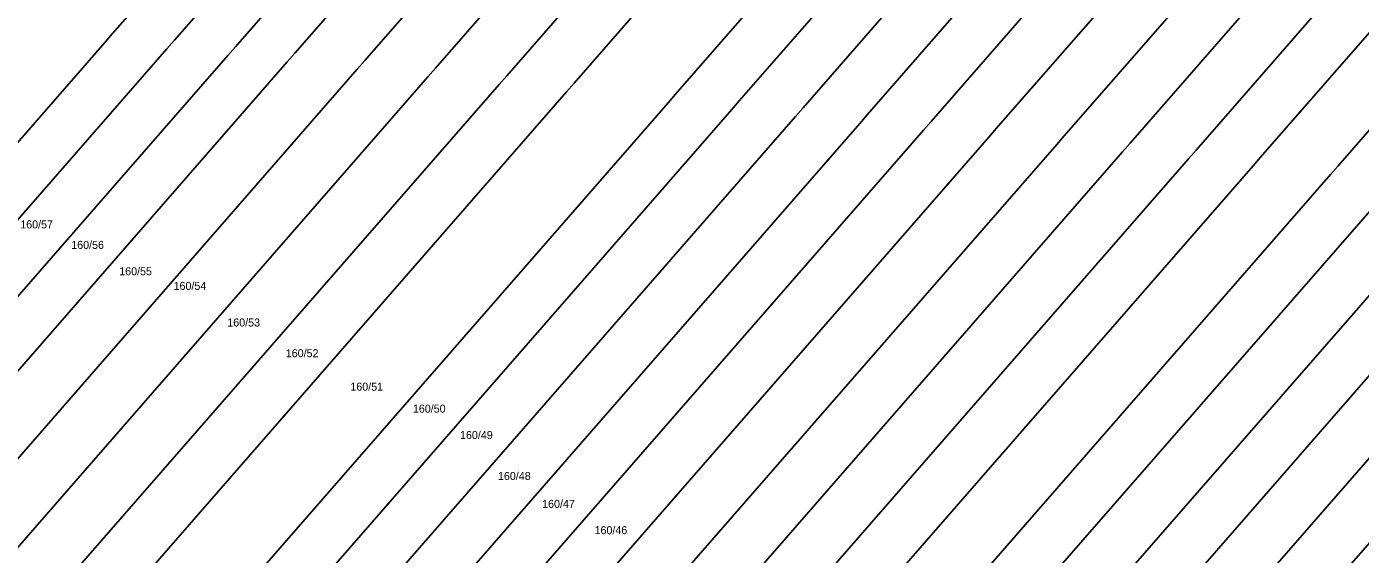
# Model space of a CAD drawing. Extents: x -580630 to -576196, y -1189024 to -1183567.
# Drawn here: x -579205 to -578921.7, y -1186434.7 to -1186322.7 of the extents above; entities that cross this region are included whole.
import ezdxf

# ---------------------------------------------------------------- set-up
doc = ezdxf.new("R2010")
doc.units = 0
doc.layers.add('Vrstva 1', color=7, linetype='Continuous')
doc.layers.add('Vrstva 18', color=7, linetype='Continuous')

msp = doc.modelspace()

# ---------------------------------------------------------------- linework, layer by layer
at = {"layer": 'Vrstva 1'}
for p, q in [((-579072.75, -1186193.55), (-579186.75, -1186324.12)), ((-579173.64, -1186325.54), (-579064.19, -1186200.17)), ((-579055.7, -1186206.72), (-579160.66, -1186326.94)), ((-579148.04, -1186328.3), (-579047.45, -1186213.09)), ((-579037.75, -1186220.59), (-579133.17, -1186329.9)), ((-579118.17, -1186331.51), (-579027.95, -1186228.17)), ((-579018.06, -1186235.81), (-579103.03, -1186333.14)), ((-579088.71, -1186334.68), (-579008.7, -1186243.04)), ((-578994.61, -1186253.92), (-579067.14, -1186336.99)), ((-579053.63, -1186338.44), (-578985.79, -1186260.74)), ((-578976.94, -1186267.58), (-579040.08, -1186339.9)), ((-579026.43, -1186341.37), (-578968.02, -1186274.47)), ((-579012.88, -1186342.83), (-578959.17, -1186281.31)), ((-578950.11, -1186288.31), (-578999.01, -1186344.32)), ((-578940.68, -1186295.6), (-578984.57, -1186345.87)), ((-578970.56, -1186347.38), (-578931.53, -1186302.67)), ((-578922.38, -1186309.74), (-578956.56, -1186348.89)), ((-578942.87, -1186350.39), (-578913.42, -1186316.66)), ((-579186.75, -1186324.12), (-579188.35, -1186325.96)), ((-579188.35, -1186325.96), (-579421.07, -1186592.52)), ((-579409.69, -1186595.92), (-579175.24, -1186327.38)), ((-579175.24, -1186327.38), (-579173.64, -1186325.54)), ((-579160.66, -1186326.94), (-579162.27, -1186328.78)), ((-578902.72, -1186325.1), (-578926.41, -1186352.23)), ((-579162.27, -1186328.78), (-579398.42, -1186599.28)), ((-579387.47, -1186602.56), (-579149.65, -1186330.14)), ((-579149.65, -1186330.14), (-579148.04, -1186328.3)), ((-579133.17, -1186329.9), (-579134.78, -1186331.74)), ((-579134.78, -1186331.74), (-579374.58, -1186606.41)), ((-579119.78, -1186333.35), (-579118.17, -1186331.51)), ((-579103.03, -1186333.14), (-579104.64, -1186334.98)), ((-579361.57, -1186610.3), (-579119.78, -1186333.35)), ((-579104.64, -1186334.98), (-579348.43, -1186614.22)), ((-579090.32, -1186336.52), (-579088.71, -1186334.68)), ((-579336, -1186617.93), (-579090.32, -1186336.52)), ((-579068.75, -1186338.83), (-579317.29, -1186623.52)), ((-579067.14, -1186336.99), (-579068.75, -1186338.83)), ((-579055.23, -1186340.29), (-579053.63, -1186338.44)), ((-579305.56, -1186627.03), (-579055.23, -1186340.29)), ((-579040.08, -1186339.9), (-579041.69, -1186341.74)), ((-579028.03, -1186343.21), (-579026.43, -1186341.37)), ((-579041.69, -1186341.74), (-579293.82, -1186630.54)), ((-579281.96, -1186634.07), (-579028.03, -1186343.21)), ((-579014.49, -1186344.67), (-579012.88, -1186342.83)), ((-578999.01, -1186344.32), (-579000.62, -1186346.16)), ((-579270.17, -1186637.53), (-579014.49, -1186344.67)), ((-579000.62, -1186346.16), (-579258.08, -1186641.07)), ((-578984.57, -1186345.87), (-578986.18, -1186347.71)), ((-578986.18, -1186347.71), (-579126.07, -1186507.95)), ((-579116.77, -1186514.85), (-578972.17, -1186349.22)), ((-578972.17, -1186349.22), (-578970.56, -1186347.38)), ((-578956.56, -1186348.89), (-578958.17, -1186350.73)), ((-578958.17, -1186350.73), (-579107.47, -1186521.74)), ((-579098.36, -1186528.5), (-578944.47, -1186352.23)), ((-578944.47, -1186352.23), (-578942.87, -1186350.39)), ((-578926.41, -1186352.23), (-578928.01, -1186354.07)), ((-578928.01, -1186354.07), (-579087.4, -1186536.63)), ((-579078.22, -1186543.44), (-578914.24, -1186355.61)), ((-578900.1, -1186357.18), (-579068.8, -1186550.42)), ((-579059.81, -1186557.09), (-578886.6, -1186358.69)), ((-578872.65, -1186360.25), (-579050.52, -1186563.98)), ((-579040.97, -1186571.07), (-578858.31, -1186361.85))]:
    msp.add_line(p, q, dxfattribs=at)

# ---------------------------------------------------------------- texts
at = {"layer": 'Vrstva 18'}
for s, p in [('160/57', (-579206.388, -1186365.5)), ('160/56', (-579195.548, -1186369.85)), ('160/55', (-579185.355, -1186375.45)), ('160/54', (-579173.808, -1186378.55)), ('160/53', (-579162.395, -1186386.32)), ('160/52', (-579149.972, -1186392.84)), ('160/51', (-579136.25, -1186399.94)), ('160/50', (-579122.965, -1186404.6)), ('160/49', (-579112.951, -1186410.2)), ('160/48', (-579104.891, -1186418.9)), ('160/47', (-579095.511, -1186424.81)), ('160/46', (-579084.371, -1186430.39))]:
    msp.add_text(s, height=1.7, dxfattribs=at).set_placement(p)

doc.saveas('drawing.dxf')
